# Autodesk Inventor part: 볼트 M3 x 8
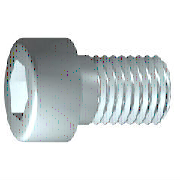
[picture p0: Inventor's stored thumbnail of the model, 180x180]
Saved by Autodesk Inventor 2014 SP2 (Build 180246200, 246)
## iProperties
IsCustomPart: 0
Created: 2012-02
Part Number: 볼트 M3 x 8
Material: 스테인리스강
Description: 6각 소켓 머리 캡 나사
Document SubType Name: Modeling
Standard: ISO 4762
Designer: mduedu
Standard Revision: Fourth edition 2004-03-01
Standards Organization: ISO
Language: ko-KR
Size Designation: M3 x 8
Categories: <MemberInstance><Categories><Category DisplayName="조임쇠" InternalName="e4da775c-781d-43d5-af7c-5136215cf5a6" Mnemonic="FSTN"><Category DisplayName="볼트" InternalN
Density: 8.08 g/cm^3
Appearance: 반광택
Author: mduedu
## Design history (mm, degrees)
sketch "스케치1"
  geometry: L1 (-0.867, 0)-(8, 0); L2 (8, 0)-(8, 1.5); L3 (8, 1.5)-(1.25, 1.5); L4 (1.25, 1.5)-(0.943, 1.5); L5 (0.943, 1.5)-(0, 1.5); L6 (0, 1.5)-(0, 2.75); L7 (0, 2.75)-(-3, 2.75); L8 (-3, 2.75)-(-3, 1.443); L9 (-3, 1.443)-(-1.7, 1.443); L10 (-1.7, 1.443)-(-0.867, 0); L11 (-5.2, 0)-(10.2, 0) reference; L12 (0, -0.55)-(0, 3.3) reference; L13 (1.25, 1.5)-(0, 1.5)
  constraints: 22 end point, 6 parallel, 2 collinear, 2 perpendicular, 1 horizontal, 1 point on line
  dimensions: "d1" = 6.75 distance from line of L3.end L2 (= GEL); "d2" = 0.30683 distance of L4.end L3.end (computed from GAL); "d3" = 3 distance between parallel lines of L8 L6 (= KOH); "d4" = 1.3 distance of L8.end L9.end (= INTI); "d5" = 60 deg angle of L10 L1; "d6" = 3 diameter of L3 L1 (= GD); "d7" = 3 diameter of L5 L1 (= BDM); "d8" = 2.88675 diameter of L9 L1 (= 1.1547 x SW); "d9" = 5.5 diameter of L7 L1 (= KOD); "d26" = 8 distance between parallel lines of L12 L2 (= NLG)
revolve "본체" sketch "스케치1" stored, may be unused: angle "d10" = 90 deg
sketch "스케치2"
  geometry: L1 (0, -3.85)-(0, 3.85) reference; L2 (-3.85, 0)-(3.85, 0) reference; L3 (1.443, 0)-(0.722, -1.25); L4 (0.722, -1.25)-(-0.722, -1.25); L5 (-0.722, -1.25)-(-1.443, 0); L6 (-1.443, 0)-(-0.722, 1.25); L7 (-0.722, 1.25)-(0.722, 1.25); L8 (0.722, 1.25)-(1.443, 0); 2 further points
  constraints: 12 end point, 1 coincident, 1 horizontal alignment, 1 point on line, 12 other
extrude "슬롯" join sketch "스케치2" stored distance "d11" = 10; taper "d12" = 0 deg
workplane "Work Plane1"
fillet "Fillet2" dims "d30" = 0.1 (= R)
body "Solid1"
fillet "모깎기1" dims "d17" = 0.3 (= RR)
feature "스레드" dims "d13" = 6.75 (= GEL), "d14" = 0
chamfer "모따기1" distance "d15" = 0.30673 (= -0.5 x SPD + 0.5 x GD); stored, may be unused: second distance "d16" = 0.30673 (= GUL), angle "d27" = 45 deg
other parameters: "GD" = 3 [user parameter; used in 2 equation terms], "NLG" = 8 [user parameter; used in 1 equation term], "GEL" = 6.75 [user parameter; used in 2 equation terms], "KOD" = 5.5 [user parameter; used in 1 equation term], "KOH" = 3 [user parameter; used in 1 equation term], "INTI" = 1.3 [user parameter; used in 1 equation term], "GAL" = 0.30673 (= 0.61345 x PTC) [user parameter; used in 1 equation term], "GUL" = 0.30673 (= 0.61345 x PTC) [user parameter; used in 1 equation term], "BDM" = 3 (= NND) [user parameter; used in 1 equation term], "SW" = 2.5 [user parameter; used in 2 equation terms], "RR" = 0.3 [user parameter; used in 1 equation term], "SPD" = 2.38655 (= NND - 1.2269 x PTC) [user parameter; used in 1 equation term], "d19" = 0, "d28" = 0, "d29" = 0, "R" = 0.1 [user parameter; used in 1 equation term], "TOA" = 30 deg [user parameter], "GD1" = 2.38655 (= THREADDIA - 1.2269 x PTC) [user parameter], "THREADDIA" = 3 [user parameter; used in 1 equation term], "FAWI" = 45 deg [user parameter], "PTC" = 0.5 [user parameter; used in 5 equation terms], "NND" = 3 [user parameter; used in 2 equation terms], "E0" = 2.8875 (= 1.155 x SW) [user parameter]
